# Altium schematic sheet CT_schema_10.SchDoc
size 277 x 170 mm
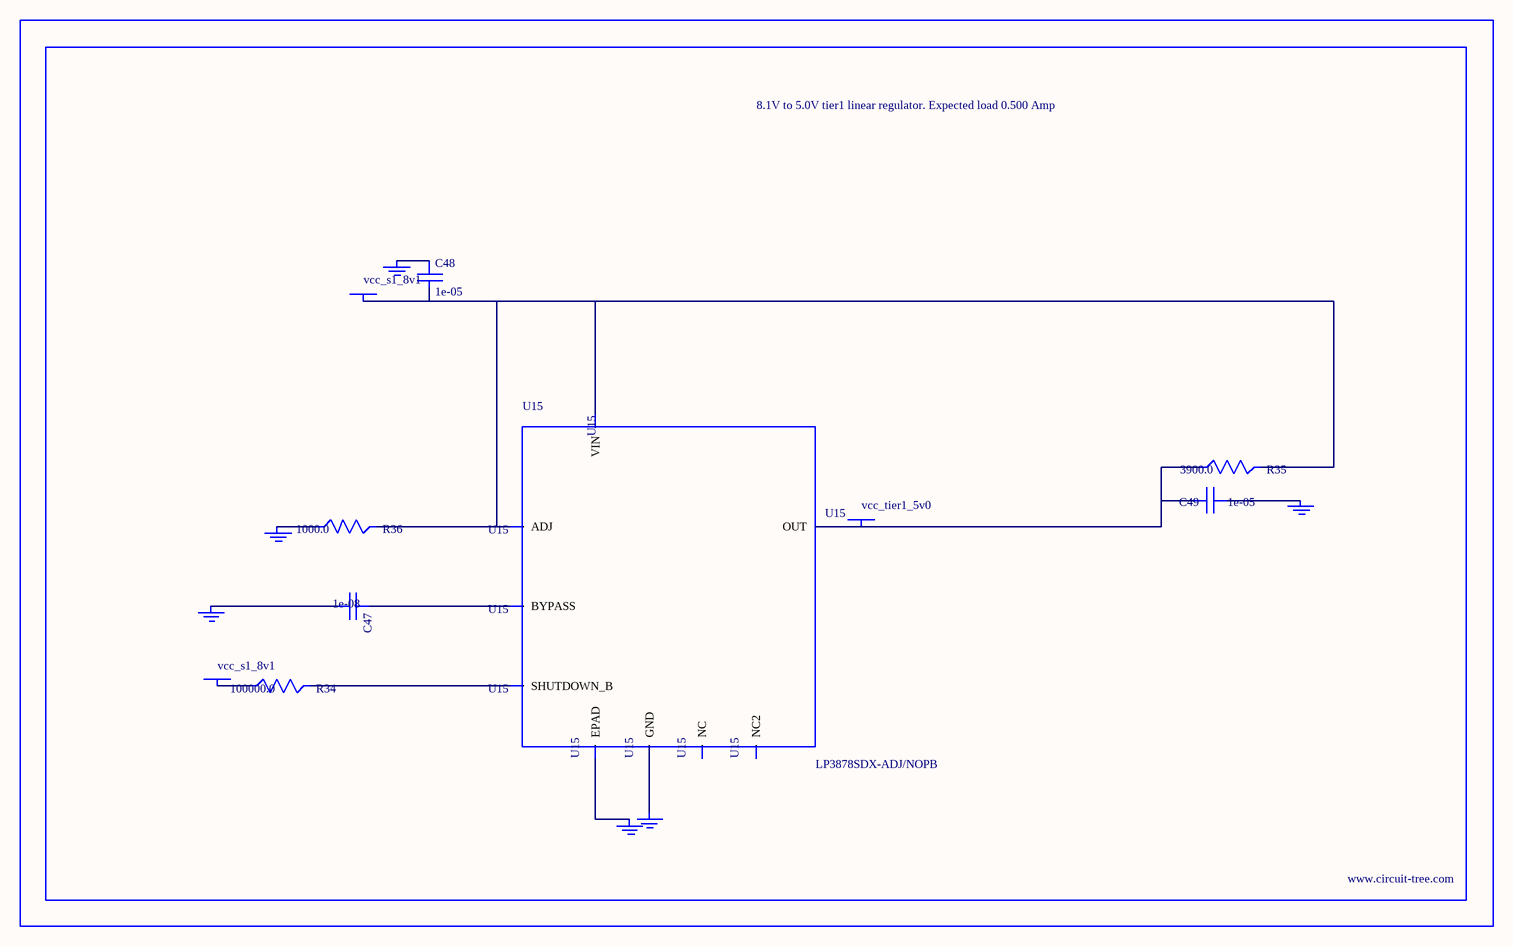
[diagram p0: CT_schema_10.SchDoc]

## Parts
BORDER9  (no value)
C47  1e-08  [C0402]
C48  1e-05  [C1206]
C49  1e-05  [C1210]
GND_INSTANCE_9_0  (no value)
GND_INSTANCE_9_1  (no value)
GND_INSTANCE_9_2  (no value)
GND_INSTANCE_9_3  (no value)
GND_INSTANCE_9_4  (no value)
GND_INSTANCE_9_5  (no value)
POWER_INSTANCE_9_0  vcc_s1_8v1
POWER_INSTANCE_9_1  vcc_s1_8v1
POWER_INSTANCE_9_2  vcc_tier1_5v0
R34  100000.0  [R0603]
R35  3900.0  [R0603]
R36  1000.0  [R0603]
U15  LP3878SDX-ADJ/NOPB  [WSON-8]

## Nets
NetC47_1: C47.1 U15.1(BYPASS)
NetC47_2: C47.2 GND_INSTANCE_9_0.0(GND)
NetC48_1: C48.1 GND_INSTANCE_9_1.0(GND)
NetC48_2: C48.2 POWER_INSTANCE_9_0.0(PWR) R35.2 R36.2 U15.4(VIN) U15.6(ADJ)
NetC49_1: C49.1 GND_INSTANCE_9_2.0(GND)
NetC49_2: C49.2 POWER_INSTANCE_9_2.0(PWR) R35.1 U15.5(OUT)
NetGND_INSTANCE_9_3_0: GND_INSTANCE_9_3.0(GND) R36.1
NetGND_INSTANCE_9_4_0: GND_INSTANCE_9_4.0(GND) U15.PAD(EPAD)
NetGND_INSTANCE_9_5_0: GND_INSTANCE_9_5.0(GND) U15.3(GND)
NetPOWER_INSTANCE_9_1_0: POWER_INSTANCE_9_1.0(PWR) R34.1
NetR34_2: R34.2 U15.8(SHUTDOWN_B)

Not connected (* = marked no-connect by the designer): U15 2(NC) 7(NC2)

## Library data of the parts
BORDER9 = BORDER_PAGE9
C47 = C0402C103K3RAC
C48 = C1206C106K3RACTU
C49 = GRM32DR61E106MA12L
GND_INSTANCE_9_0-GND_INSTANCE_9_5 = GND
POWER_INSTANCE_9_0-POWER_INSTANCE_9_2 = PWR
R34 = RC0603JR-07100KL
R35 = RC0603JR-073K9L
R36 = RC0603JR-071KL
